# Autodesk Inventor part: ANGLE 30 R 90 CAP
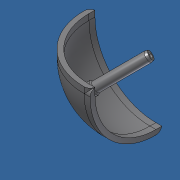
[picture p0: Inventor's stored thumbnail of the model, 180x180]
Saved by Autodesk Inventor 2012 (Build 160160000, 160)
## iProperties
Created: 2012-08
Part Number: ANGLE 30 R 90 CAP
Document SubType Name: Modeling
Designer: Administrator
Density: 1.06 g/cm^3
Material: ABS Plastic
Mass: 3.33872 g
Surface Area: 36.4451 cm^2
Volume: 3.14974 cm^3
Author: Administrator
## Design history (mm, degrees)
feature "Base1"
body "Solid1"
